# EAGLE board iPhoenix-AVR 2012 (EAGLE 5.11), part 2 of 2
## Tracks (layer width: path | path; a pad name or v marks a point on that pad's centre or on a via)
+5V  (via drill 0.5 pad 1.27)
  Top 0.254: v87.95,99.06 v92.71,94.3 | v53.66,73.03 v64.77,73.03 | v12.7,75.88 v12.7,66.67 | v31.75,37.15 v35.24,33.66 | v89.85,103.19 v96.52,103.19
  Bottom 0.406: 61.49,99.38 arc45 60.59,99.01 60.43,98.85 arc45 60.06,97.95 IC1.4 | 59.74,111.5 arc45 59.37,110.6 59.37,108.63 arc-45 59,107.74 56.96,105.69 arc45 56.81,105.34 IC1.20
  Bottom 0.61: 99.3,116.91 PS1.4 | LCD.2 | GLCD.4 | 68.58,95.37 R1.2 | LCD.2 | 154.3,84.14 153.67,84.77
  Bottom 0.813: 99.3,116.91 100.59,115.62 arc-45 100.96,114.73 100.96,111.44 R39.1 | C39.+ IC9.16 | 74.29,110.17 C35.1 arc90 69.53,108.59 69.53,106.25 arc45 69.9,105.36 arc-45 70.17,104.72 70.17,100.97 arc-90 C5.+ | 74.29,110.17 C36.+ 86.29,110.17 arc-45 87.5,109.67 89.33,107.84 arc-45 89.85,106.57 v89.85,103.19 89.85,101.49 arc-45 89.48,100.59 v87.95,99.06 | 74.29,110.17 IC8.8 | C1.2 61.49,99.38 | C2.2 59.74,111.5 | R30.2 19.31,39.42
  Bottom 1.016: R12.2 108.32,20.06 arc45 107.95,19.16 IC4.1 107.95,14.18 arc-45 107.58,13.28 C22.+ 106.68,6.67 | 100.33,86.04 C21.+ | 100.33,86.04 IC3.VCC 96.41,86.04 arc-45 95.51,86.41 92.45,89.48 arc-45 92.07,90.38 ISP.1 92.07,93.14 arc-45 92.45,94.03 v92.71,94.3 | 100.33,86.04 R15.2 | 100.96,111.44 C37.1 R35.2 | 64.13,123.51 LED1.A | 64.13,123.51 C2.2 67.42,115.89 arc-45 68.32,115.52 R34.2 C35.1 | C28.1 8.89,109.75 arc45 9.26,108.85 11.06,107.05 arc-45 11.43,106.15 11.43,101.81 arc-45 11.06,100.91 10.16,100.01 | C28.1 JBUZ.2 | LED12.A D2.C 10.16,100.01 | C32.+ C33.1 13.97,53.97 | C32.+ 16.62,60.01 arc-45 17.52,59.64 R32.2 | R29.2 IC7.8 14.92,53.02 | C34.2 C31.+ | IC9.10 141.6,91.01 arc45 141.98,90.12 144.41,87.68 arc45 145.31,87.31 C40.2 150.18,87.31 arc-45 151.8,86.64 153.67,84.77 | GLCD.4 36.2,16.08 arc-45 35.82,15.19 35.3,14.66 arc-45 34.4,14.29 32.91,14.29 arc45 32.01,13.92 31.49,13.39 arc45 31.11,12.49 LCD.2 31.11,6.88 arc45 31.49,5.98 33.28,4.18 arc45 34.18,3.81 JLEDD.2 | GLCD.4 36.19,18.84 arc45 35.82,19.74 34.66,20.9 arc-45 34.29,21.8 R52.E 34.29,32.7 v35.24,33.66 | 12.7,77.79 C19.1 5VA1.2 23.6,77.79 arc45 24.5,78.16 K1.1 34.29,84.14 | C1.2 C5.+ 68.58,95.37 | 41.91,87.31 43.18,87.31 | 43.18,87.31 46.39,87.31 arc-45 47.79,86.73 49.84,84.68 arc-45 50.8,82.36 50.8,77.26 arc45 51.77,74.91 v53.66,73.03 | 142.88,6.67 134.83,6.67 arc-45 133.93,7.04 R10.2 127.69,7.04 arc-45 126.79,6.67 124.35,6.67 arc-45 123.45,7.04 C26.1 IC5.1 119.38,7.83 arc-45 119.01,6.93 118.48,6.4 arc-45 117.58,6.03 107.31,6.03 | 142.88,6.67 R8.2 | 153.67,83.5 154.3,84.14 154.94,84.77 | 154.94,84.77 156.22,86.05 arc45 156.84,87.56 C39.+
  Bottom 1.016: 153.67,83.5 153.45,83.28 arc45 153.03,82.28 153.03,75.14 arc-45 152.66,74.24 152.14,73.71 arc-45 151.24,73.34 147.85,73.34 arc45 146.95,72.97 143.88,69.9 arc45 143.51,69.01 143.51,66.25 arc-45 143.14,65.35 142.61,64.82 arc-45 141.71,64.45 138.32,64.45 arc45 137.42,64.08 134.36,61.01 arc45 133.98,60.12 133.98,58.28 arc-90 131.27,55.56 128.8,55.56 arc45 127.9,55.19 127.4,54.7 arc45 126.74,53.09 126.74,52.97 arc45 127.19,51.88 127.23,51.84 arc45 128.98,51.12 140.47,51.12 arc-45 143.49,49.87 R25.A 149.17,44.5 arc-45 149.54,43.61 149.54,39.08 arc-45 149.08,37.95 148.57,37.44 arc45 148.27,36.73 148.27,33.55 arc-45 147.9,32.65 R17.A 148.42,30.96 arc-45 149.54,28.71 149.54,19.58 arc-45 149.17,18.68 147.69,17.2 arc45 147.32,16.3 147.32,9.73 arc-45 146.95,8.84 145.15,7.04 arc-45 144.25,6.67 142.88,6.67 | 106.04,6.03 107.31,6.03 | 106.04,6.03 97.1,6.03 arc-45 95.03,6.89 83.34,18.57 arc-45 82.55,20.49 R38.2 80.01,21.91 | 107.31,6.03 106.68,6.67 | 106.04,6.03 106.68,6.67 | 78.74,21.91 80.01,21.91 | 78.74,21.91 77.36,21.91 arc-45 76.46,22.28 74.35,24.39 arc45 73.45,24.77 71.33,24.77 arc-45 70.43,25.14 69.59,25.98 arc-45 69.21,26.88 C13.+ C14.1 IC2.30 69.21,41.7 arc-45 69.59,42.6 71.38,44.4 arc45 71.75,45.29 IC2.10 C12.1 71.75,56.31 arc-45 72.13,57.2 73.29,58.37 arc45 73.66,59.26 C11.+ 73.66,63.29 arc45 73.29,64.19 64.99,72.48 arc-45 v64.77,73.03 | 79.38,22.54 C38.2 | 80.01,21.91 79.38,22.54 | 78.74,21.91 79.38,22.54 | 64.13,123.51 LED2.A 39.26,123.51 arc45 38.36,123.14 PW1.3 C18.+ C17.+ C16.1 R7.2 | 13.97,53.97 13.97,53.02
  Bottom 1.016: 13.97,53.02 14.92,53.02 | 13.97,63.18 13.97,62.23 | 13.97,62.23 C32.+ | v12.7,66.67 13.6,65.78 arc-45 13.97,64.88 13.97,64.13 | 13.97,64.13 13.97,63.18 | 12.7,77.79 v12.7,75.88 | 13.97,63.18 13.02,63.18 | 13.02,63.18 JP8.1 | 19.31,39.42 arc-45 19.68,38.53 R31.2 18.79,36.25 arc45 18.41,35.35 IC6.8 17.07,34.93 arc45 16.12,34.53 15.62,34.04 arc45 15.24,33.11 C34.2 | 13.97,53.02 13.97,52.07 | 13.97,52.07 13.97,46.14 arc45 14.94,43.8 R30.2 | C34.2 25,32.38 arc45 28.39,33.79 v31.75,37.15 | R7.2 38.47,100.38 arc-45 37.57,100.01 22.06,100.01 arc41 21.23,99.71 19.72,98.41 arc-41 18.9,98.11 12.59,98.11 arc-45 11.69,98.48 10.16,100.01 | R7.2 41.22,101.34 arc-45 41.91,99.49 41.91,88.58 | 41.91,88.58 41.91,87.31 | 153.67,83.5 153.67,84.77 | 153.67,84.77 154.94,84.77 | 12.7,77.79 8.12,77.79 arc-45 7.22,78.16 +5V.2 | R39.1 100.33,109.11 arc-45 98.83,105.5 v96.52,103.19 | 41.91,87.31 40.64,87.31 | 40.64,87.31 37.17,87.31 arc45 36.2,86.91 34.58,85.29 arc45 34.29,84.6 34.29,84.14 | 34.29,84.14 D1.C | 41.91,88.58 40.64,87.31 | 41.91,88.58 43.18,87.31 | 13.97,64.13 13.02,63.18 | 13.02,63.18 13.97,62.23 | 14.92,53.02 13.97,52.07 | 13.97,53.97 14.92,53.02 | C28.1 8.91,115.25 SPK.1
+5V/1  (via drill 0.5 pad 1.27)
  Top 0.254: v40.96,107.63 v33.02,107.63
  Bottom 1.016: JP7.3 C3.1 30.74,108 arc45 31.64,107.63 v33.02,107.63 | R2.2 47.47,107.48 FB1.1 41.11,107.48 v40.96,107.63
A1
  Bottom 0.813: DSP1.13 128.27,122.3 arc-45 128.59,123.06 129.8,124.28 arc-45 131.01,124.78 141.71,124.78 arc-45 143.15,124.18 146.03,121.3 arc45 146.84,120.97 152.03,120.97 arc-45 153.74,120.26 R45.2
A2
  Bottom 0.813: DSP1.9 138.43,122.36 arc-90 139.57,123.51 141.4,123.51 arc-45 142.29,123.14 145.19,120.24 arc45 146.5,119.7 151.09,119.7 arc-45 152.24,119.22 R46.2
A2P
  Bottom 0.508: 139.16,108.27 135.97,108.27 arc90 134.62,106.92 134.62,105.28 arc-90 133.47,104.14
  Bottom 0.813: 139.16,108.27 arc-45 140.08,107.88 140.63,107.33 arc-45 140.97,106.52 DSP1.7
  Bottom 1.016: S7SEG1.1 128.27,101.39 arc-45 128.64,102.29 129.95,103.6 arc-45 131.26,104.14 133.47,104.14
A3
  Bottom 0.813: DSP1.4 133.35,107.5 arc-45 134.12,109.35 136.3,111.54 arc-45 138.37,112.39 143.79,112.39 arc45 147.1,113.77 R47.2
A4
  Bottom 0.813: R48.2 145.59,114.79 arc-45 142.87,113.66 134.56,113.66 arc45 132.49,112.81 129.07,109.38 arc45 128.27,107.45 DSP1.2
A5
  Bottom 0.813: R49.2 143.78,115.52 arc-45 142.36,114.94 134.18,114.94 arc45 131.67,113.9 126.41,108.63 arc45 125.73,106.99 DSP1.1
A6
  Bottom 0.61: 136.16,123.51 arc-90 137.16,122.5 137.16,120.12
  Bottom 0.813: DSP1.12 130.81,122.36 arc-90 131.95,123.51 136.16,123.51 | 137.16,120.12 arc45 137.91,118.31 139.55,116.67 arc45 140.67,116.2 141.92,116.2 arc90 R50.2
A7
  Bottom 1.016: R51.2 DSP1.5
A8
  Bottom 1.016: R53.2 DSP1.8
AR11
  Bottom 1.016: 75.59,116.55 RS1.1 R34.1 | 75.59,116.55 R37.2 | 75.59,116.55 76.46,115.68 arc-45 76.83,114.78 IC8.7
CB2
  Bottom 0.406: IC1.13 54.21,96.14 arc-45 53.84,95.24 arc-45 53.1,94.93 52.11,94.93 arc45 51.22,94.56 49.23,92.58
  Bottom 0.813: 49.23,92.58 arc45 JP2.2
CB3
  Bottom 0.406: IC1.14 53.56,96.47 arc-45 53.41,96.1 arc-45 52.51,95.73 50.15,95.73 arc45 49.26,95.35 46.73,92.83
  Bottom 0.813: 46.73,92.83 arc45 46.35,91.93 JP2.3
CB4
  Bottom 0.406: IC1.12 54.86,95.5 arc-45 54.49,94.6 54.3,94.41 arc-45 53.65,94.14 arc45 52.75,93.77 51.81,92.82
  Bottom 0.813: 51.81,92.82 arc45 51.43,91.93 JP2.1
CTS
  Bottom 0.406: IC1.11 55.51,94.86 arc-45 55.14,93.96 54.35,93.17
  Bottom 0.813: JP1.1 53.97,92.27 arc-45 54.35,93.17
  Bottom 1.016: JP1.1 S22.6
DCD
  Bottom 0.406: 56.16,92.11 IC1.10
  Bottom 0.813: 56.16,92.11 JP1.2
DSR
  Bottom 0.406: 59.05,91.87 JP1.3 | 58.68,92.76 57.18,94.27 arc-45 56.81,95.16 IC1.9
  Bottom 0.813: 58.68,92.76 arc-45 59.05,91.87
DTR
  Bottom 0.406: IC1.2 61.36,95.06 arc45 61.73,94.16 JP0.1
EPROM_WP  (via drill 0.5 pad 1.27)
  Top 0.254: v18.41,46.04 v18.41,49.21
  Bottom 0.813: S21.2 26.09,46.62 arc45 25.19,46.99 20.71,46.99 arc45 v18.41,46.04
  Bottom 1.016: IC7.7 R32.1 v18.41,49.21
GLCD-V0
  Bottom 1.016: GLCD.5 38.74,19.48 arc45 38.36,20.37 R52.S
GLCD-VEE  (via drill 0.5 pad 1.27)
  Top 0.254: v40,21.59 v71.75,21.59
  Bottom 0.61: GLCD.18
  Bottom 1.016: v71.75,21.59 GLCD.18 | v40,21.59 39.74,21.85 arc-45 39.37,22.75 R52.A
GND  (via drill 0.5 pad 1.27)
  Top 0.254: v42.86,121.6 v42.86,125.41 | v29.84,104.14 v29.84,98.11 | v40,98.11 v43.81,98.11 | v87.95,106.36 v90.17,109.54 | v86.2,98.27 v90.33,94.14 | v148.27,93.66 v151.45,95.88 | v155.89,97.16 v159.38,95.57 | v68.9,112.39 v68.9,117.47 | v104.46,4.13 v104.46,7.94 | v147.32,20.96 v151.45,20.96 | v48.89,80.64 v52.7,80.64 | v31.11,3.49 v34.29,5.71 | v43.81,76.52 v47.31,74.93 | v117.79,50.48 v122.55,50.48 | v72.07,42.23 v69.21,45.08
  Bottom 0.406: IC1.18 55.51,102.92 56.51,101.92 | IC1.21 57.46,102.23 57.15,101.92 | IC1.26 60.71,102.17 60.96,101.92 | IC1.25 60.06,102.29 59.69,101.92 | IC1.7 58.11,101.59 57.78,101.92 | v68.9,117.47 68.9,118.43 | v104.46,4.13 104.46,2.54 | v151.45,20.96 153.35,20.96
  Bottom 0.508: 140.97,13.39 141.87,14.29 145.41,14.29
  Bottom 0.61: C38.1 | LCD.16 68.9,11.75 69.85,12.7 72.39,12.7 76.83,16.19 GLCD.20 | v147.32,20.96 147.32,20 | LCD.1 | LCD.1 | 132.55,13.2 137.81,8.25 139.55,8.25 140.97,9.36 | C35.2 71.66,108.18 arc-45 73.42,108.9 84.45,108.9 C36.- 85.09,107 R33.1 85.41,97.16 v86.2,98.27 | ISP.2 89.53,93.98 91.76,96.2 93.34,96.2 | C16.2 31.11,105.09 | v42.86,125.41 42.23,125.41 | v43.81,98.11 C10.2 | v40,98.11 39.37,98.11 | 87.63,104.78 v87.95,106.36 | v90.33,94.14 90.49,93.66 90.17,93.35 | 37.15,82.87 37.15,83.19 36.51,83.82
  Bottom 0.813: C8.2 C9.2 | v159.38,95.57 159.7,96.2
  Bottom 1.016: Q7.1 121.92,112.08 Q8.1 115.57,114.62 113.66,116.52 Q9.1 105.41,117.79 | IC4.3 102.87,13.65 C22.- 104.14,8.25 v104.46,7.94 | R26.2 C29.2 128.27,11.75 129.54,13.02 C25.2 LDR.2 132.55,13.2 | R26.2 C26.2 | R26.2 121.92,14.29 D4.C | 145.1,27.62 C27.1 | 145.1,27.62 146.68,27.62 R17.E v147.32,20.96 145.41,19.05 C24.1 145.41,14.29 145.41,10.48 NTC.1 | C30.1 146.68,41.59 R25.E 145.1,38.74 145.1,27.62 | C21.- IC3.GND 95.88,88.58 94.61,89.85 94.61,94.93 93.34,96.2 | C39.- 152.4,88.58 151.13,89.85 C40.1 IC9.13 149.22,92.71 v148.27,93.66 | C18.- C17.- C16.2 30.8,105.09 v29.84,104.14 | Q4.1 22.86,103.82 24.76,105.73 LED11.K 26.67,106.36 C3.2 31.11,105.09 | JP8.2 C20.2 | C32.- C33.2 11.43,54.29 10.16,53.02 IC7.1 IC7.2 IC7.3 IC7.4 8.89,31.11 10.16,29.85 C31.- | IC6.4 26.03,28.57 24.76,29.85 C34.1 C31.- | IC2.11 C12.2 69.21,56.83 71.12,58.74 C11.- 71.12,63.82 69.85,65.09 C6.2 C7.2 62.86,73.4 arc-90 64.72,75.25 71.75,75.25 | C4.1 71.75,75.25 | 71.75,75.25 71.75,77.81 | R40.1 89.29,116.91 PS1.3 92.48,118.2 93.34,119.06 102.23,119.06 103.5,117.79 105.41,117.79 | R40.1 IC8.5 | 105.41,117.79 C37.2 | IC2.31 C14.2 C13.- 74.29,27.62 | C38.1 76.83,25.08 74.29,27.62 | 74.29,27.62 C15.2 | R36.1 26.67,7.94 28.57,9.84 LCD.1 | GND.1 GND.2 5VA1.1 C19.2 14.31,74 | C5.- C1.1 60.96,101.92 59.69,101.92 57.78,101.92 57.15,101.92 56.51,101.92 | 140.97,9.36 140.97,13.39 | Q6.1 131.44,99.06 132.71,97.79 137.48,97.79 IC9.8 | C31.- 11.43,19.37 BAT.- | R3.2 41.91,113.35 40,115.25 40,118.75 v42.86,121.6 | v29.84,98.11 30.48,97.79 | R40.1 87.63,112.71 v90.17,109.54 | v151.45,95.88 v155.89,97.16 | R6.2 arc45 66.49,108.08 67.98,109.57 arc45 68.9,111.79 v68.9,112.39
  Bottom 1.016: 40,80.01 42.23,80.01 v43.81,76.52 | v47.31,74.93 v48.89,80.64 | v52.7,80.64 54.29,80.64 | S20.4 S20.3 | S18.4 S18.3 | S19.3 48.62,64.81
  Bottom 1.676: 1.59,80.64 1.59,95.88
  pour Bottom (isolate 0.711): 166.69,134.3 168.27,-6.03 -6.99,-7.3 -8.57,81.91 18.73,81.91 22.86,86.36 22.86,95.25 5.4,96.2 5.4,93.98 -8.57,93.98 -8.57,133.03
GROUP-A1
  Bottom 1.016: R23.1 JRLY.2
IR
  Bottom 1.016: JRC5R.1 R15.1 98.32,91.76 arc45 97.42,91.39 IC3.OUT
LCDA
  Bottom 0.61: R38.1 | GLCD.19
  Bottom 0.813: LCD.15 64.13,12.17 arc-45 64.51,13.07 65.03,13.6 arc-45 65.93,13.97 70.93,13.97 arc45 71.83,14.34 73.92,16.44 arc45 74.29,17.34 GLCD.19
  Bottom 1.016: GLCD.19 R38.1
LDR
  Bottom 1.016: R14.2 130.68,20.77 arc45 129.47,21.27 JDAC3.1 128.27,20.53 arc45 128.64,19.63 129.17,19.1 arc-45 129.54,18.21 C25.1
LM35-1
  Bottom 1.016: JDAC5.1 120.12,21.27 arc-45 121.02,20.9 124.09,17.83 arc-45 124.46,16.94 R19.2 C29.1
LM35-2
  Bottom 1.016: JDAC6.2 D3.A 113.03,17.99 arc-45 112.66,17.09 arc45 112.39,16.46 112.39,15.93 arc45 112.66,15.29 arc-45 113.03,14.4 IC5.3
N$1
  Bottom 1.016: Q5.1 IC6.1
N$2
  Bottom 0.61: Q1.1 67.94,58.86
  Bottom 1.016: IC2.12 66.67,57.07 arc-45 67.05,57.97 Q1.1 | 67.94,58.86 C6.1
N$3
  Bottom 1.016: SG1.+ 4.18,110.28 arc-45 3.81,111.17 JBUZ.1
N$4
  Bottom 1.016: JP8.3 C20.1 R9.2
N$5
  Bottom 1.016: R9.1 JDAC4.2
N$6  (via drill 0.6 pad 1.27)
  other vias: 3.49,124.46
N$7
  Bottom 1.016: Q5.2 IC6.2
N$8
  Bottom 1.016: C15.1 IC2.32
N$9
  Bottom 1.016: BAT.+ 23.87,15.5 arc-45 23.49,16.4 IC6.3
N$10  (via drill 0.6 pad 1.27)
  other vias: 158.43,124.46
N$11  (via drill 0.6 pad 1.27)
  other vias: 158.43,3.81
N$12  (via drill 0.6 pad 1.27)
  other vias: 3.49,3.81
N$13
  Bottom 0.61: X1.S2 46.68,116.54
  Bottom 1.016: 46.68,116.54 arc-45 50.49,118.11 54.91,118.11 arc-45 X1.S1 | R3.1 42.49,116.89 arc45 43.39,116.52 X1.S2
N$14
  Bottom 1.016: LED11.A 26.62,102.61 arc45 27.51,102.23 R7.1
N$15
  Bottom 1.016: JP7.1 27.76,116.52 arc45 26.86,116.15 J1.1
N$16
  Bottom 1.016: JP7.2 30.59,113.98 arc45 31.49,114.35 32.01,114.88 arc45 32.38,115.78 32.38,117.27 arc-45 32.76,118.16 33.92,119.33 arc45 34.29,120.22 PW1.2
N$17  (via drill 0.6 pad 1.27)
  other vias: 80.96,64.45
N$36
  Bottom 1.016: S2.2 S3.1
N$37
  Bottom 1.016: S3.2 S4.1
N$38
  Bottom 1.016: S4.2 S5.1
N$39
  Bottom 1.016: S10.2 S11.1
N$40
  Bottom 1.016: S11.2 S12.1
N$41
  Bottom 1.016: S12.2 S13.1
N$60
  Bottom 1.016: S6.2 S7.1
N$61
  Bottom 1.016: S7.2 S8.1
N$62
  Bottom 1.016: S8.2 S9.1
N$63
  Bottom 0.61: LCD.3
  Bottom 1.016: R36.2 LCD.3
N$65
  Bottom 1.016: S14.2 S15.1
N$66
  Bottom 1.016: S15.2 S16.1
N$67
  Bottom 1.016: S2.4 126.1,77.09 arc45 125.73,76.19 125.73,73.87 arc-45 125.36,72.97 123.84,71.45 arc-45 122.94,71.08 S6.3
N$68
  Bottom 1.016: S7.3 133.61,72.69 arc45 133.98,73.59 133.98,75.99 arc-45 134.36,76.89 137.07,79.6 arc-45 137.96,79.97 S3.4
N$69
  Bottom 1.016: S8.3 141.99,71.08 arc45 142.89,71.45 145.04,73.61 arc45 145.41,74.5 145.41,76.83 arc-45 145.79,77.73 S4.4
N$70
  Bottom 1.016: S5.4 154.99,77.41 arc45 154.62,76.51 154.62,74.19 arc-45 154.25,73.29 152.42,71.45 arc-45 151.52,71.08 S9.3
N$71
  Bottom 1.016: S16.2 S17.1
N$73
  Bottom 0.61: S14.3 123.58,53.3 arc45 124.48,53.67 126.63,55.83 arc45 127,56.72 127,59.68 arc-45 127.37,60.58 S10.4
N$74
  Bottom 1.016: S11.4 136.65,60.34 arc45 135.89,58.5 135.89,57.2 arc-45 135.18,55.49 133.69,54 arc-45 S15.3
N$75
  Bottom 1.016: S16.3 141.99,53.3 arc45 142.89,53.67 144.41,55.19 arc45 144.78,56.09 144.78,58.41 arc-45 145.15,59.31 S12.4
N$76
  Bottom 1.016: S13.4 154.68,59.31 arc45 154.3,58.41 154.3,56.09 arc-45 153.93,55.19 152.42,53.67 arc-45 151.52,53.3 S17.3
N$77
  Bottom 1.016: S6.4 arc45 128.24,70.78 125.47,68 arc45 125.09,67.1 125.09,64.98 arc-45 124.72,64.08 122.83,62.19 S10.3
N$78
  Bottom 1.016: S11.3 132.47,62.19 arc45 133.37,62.56 135.52,64.72 arc45 135.89,65.61 135.89,67.94 arc-45 136.26,68.84 S7.4
N$79
  Bottom 1.016: S8.4 145.79,68.84 arc45 145.41,67.94 145.41,65.61 arc-45 145.04,64.72 142.89,62.56 arc-45 141.99,62.19 S12.3
N$80
  Bottom 1.016: S9.4 154.68,68.2 arc45 154.3,67.3 154.3,64.45 152.42,62.56 arc-45 151.52,62.19 S13.3
N$81
  Bottom 0.813: IC9.15 154.3,92.5 arc-45 154.68,93.4 158.38,97.1 arc45 158.75,98 158.75,99.49 arc45 158.38,100.38 156.58,102.18 arc-45 156.21,103.08 R45.1
N$82
  Bottom 0.813: IC9.1 arc45 156.62,99.92 154.04,102.5 arc-45 153.67,103.4 R46.1
N$83
  Bottom 0.813: IC9.2 154.3,99.49 arc45 153.93,100.38 151.5,102.82 arc-45 151.13,103.71 R47.1
N$84
  Bottom 0.813: IC9.3 151.76,100.12 arc45 151.39,101.02 148.96,103.45 arc-45 148.59,104.35 R48.1
N$95
  Bottom 0.813: IC9.4 149.22,100.76 arc45 148.85,101.65 146.42,104.09 arc-45 146.05,104.98 R49.1
N$96
  Bottom 0.813: IC9.5 146.68,101.39 arc45 146.31,102.29 144.52,104.09 arc-45 144.14,104.98 144.14,108.38 arc45 143.77,109.27 R50.1
N$100
  Bottom 0.813: IC9.6 R51.1
N$103
  Bottom 1.016: R33.2 LED14.K
N$113
  Bottom 0.813: IC9.7 141.6,103.61 arc-45 141.98,104.51 142.19,104.72 arc45 142.56,105.62 142.56,106.79 arc45 142.19,108 141.02,109.17 arc-45 140.97,109.43 R53.1
N$114
  Bottom 1.016: Q9.3 DSP1.14
N$115
  Bottom 0.61: 133.35,121.49 DSP1.11
  Bottom 0.813: 133.35,121.49 arc-90 131.55,119.7 121.53,119.7 arc45 120.03,119.07 Q8.3
N$116
  Bottom 0.813: DSP1.10 135.89,121.38 arc-45 135.6,120.67 133.94,119.02 arc-45 132.52,118.43 129.15,118.43 arc45 127.65,117.8 Q7.3
N$117
  Bottom 1.016: Q6.3 136,100.01 arc45 136.9,100.38 138.06,101.55 arc45 138.43,102.44 DSP1.6
N$118
  Bottom 0.406: 125.73,99.27 S7SEG1.2 | 126.1,98.37 126.31,98.16 arc45 127.21,97.79 130.28,97.79 arc-45 131.18,97.42 132.98,95.62 arc45 133.88,95.25 148.7,95.25 arc-45 149.6,94.88
  Bottom 0.813: 149.6,94.88 151.39,93.08 arc-45 151.76,92.18 IC9.14
  Bottom 1.016: 126.1,98.37 arc-45 125.73,99.27
N$119
  Bottom 0.406: 145.47,93.93 arc45 144.57,94.3 133.4,94.3 arc-45 132.5,94.67 130.71,96.47 arc45 129.81,96.84 125.62,96.84 arc-45 124.72,97.21 123.56,98.37 | 123.19,99.27 S7SEG1.3
  Bottom 0.813: 145.47,93.93 146.31,93.08 arc-45 146.68,92.18
  Bottom 1.016: 146.68,92.18 IC9.12 | 123.56,98.37 arc-45 123.19,99.27
N$120
  Bottom 0.406: 120.65,99.27 S7SEG1.4 | 121.02,98.37 123.29,96.1 arc45 124.19,95.73 129.33,95.73 arc-45 130.23,95.35 131.87,93.72 arc45 132.76,93.35 143.14,93.35 arc-45 143.77,93.08 arc-45 144.14,92.18
  Bottom 1.016: 121.02,98.37 arc-45 120.65,99.27 | 144.14,92.18 IC9.11
N$122
  Bottom 1.016: R44.1 Q9.2
N$123
  Bottom 1.016: R43.1 Q8.2
N$124
  Bottom 1.016: R42.1 Q7.2
N$125
  Bottom 1.016: Q6.2 R41.1
N$126
  Bottom 0.813: S7SEG1.5 118.11,100.12 arc-45 118.48,101.02 119.01,101.55 arc-45 119.91,101.92 R41.2
N$127
  Bottom 0.813: S7SEG1.6 115.57,99.55 arc-45 115.94,100.45 120.85,105.36
  Bottom 1.016: 120.85,105.36 arc-45 121.75,105.73 R42.2
N$128
  Bottom 0.813: R43.2 116.2,103.4 arc-45 115.83,102.5 113.25,99.92 arc45 S7SEG1.7
N$129
  Bottom 1.016: S7SEG1.8 R44.2
N$130
  Bottom 1.016: IC5.2 R26.1 R19.1
N$131
  Bottom 1.016: D4.A 116.47,18.36 arc-45 117.37,18.73 D3.C
N$132
  Bottom 1.016: R17.S R16.2
N$137
  Bottom 1.016: J1W.1 R12.1 102.98,21.27 arc-45 103.88,20.9 105.04,19.74 arc-45 105.41,18.84 IC4.2
N$146
  Bottom 1.016: R13.1 R8.1 151.13,11.32 arc-45 150.76,10.42 NTC.2
N$152
  Bottom 1.016: R24.2 154.06,44.37 arc45 156.18,43.5 R25.S
N$153
  Bottom 1.016: JAN1.2 C27.2 R16.1
N$154
  Bottom 1.016: R24.1 141.87,48.31 arc-45 142.24,47.42 C30.2 JAN2.2
N$155
  Bottom 1.016: R10.1 138.33,10.9 arc-45 137.95,11.8 LDR.1 137.95,19 arc-45 138.33,19.9 R14.1
N$161
  Bottom 0.406: IC1.23 58.76,105.25 arc-45 58.89,105.56 59.19,105.86 arc-45 59.64,106.04 59.88,106.04 arc45 60.1,106.14 60.32,106.36
  Bottom 0.61: 60.32,106.36 64.04,110.08 arc-45 65.8,110.81
  Bottom 0.813: 65.8,110.81 R4.1
N$163
  Bottom 1.016: SG1.- Q4.3 | D2.A 13.87,100.12 arc-45 13.49,101.01 SG1.- | SG1.- 11.8,109.32 arc-45 11.43,110.22 C28.2 11.43,118.4 arc-45 11.8,119.3 SPK.2
N$164
  Bottom 1.016: Q4.2 R27.2
N$165
  Bottom 1.016: R27.1 JSPK.2
N$197
  Bottom 0.406: 51.59,100.65 arc45 52.49,101.02 53.84,102.37 arc45 54.21,103.27 IC1.16 54.21,106 arc45 54.12,106.22 54.07,106.27 arc-45 53.97,106.49 53.97,107
  Bottom 0.61: 53.97,107 53.97,111.13
  Bottom 0.8: 53.97,111.13 53.97,111.79 X1.2
  Bottom 0.813: C8.1 51.59,100.65
N$199
  Bottom 0.406: 52.39,103.19 53.17,103.19 arc90 53.56,103.57 IC1.15 53.56,105.28 arc45 53.4,105.67 52.97,106.1 arc-45 52.7,106.73 52.7,107.32 | 52.7,110.49 52.7,112.32 arc-45 52.98,112.99 53.5,113.51
  Bottom 0.61: 52.7,107.32 52.7,110.49
  Bottom 0.8: X1.3 53.94,113.81 arc45 53.71,113.72 53.5,113.51
  Bottom 0.813: C9.1 52.39,103.19
N$200
  Bottom 0.406: 51.9,99.06 54.49,101.65 arc45 54.86,102.54 IC1.17
  Bottom 0.813: C10.1 50.96,98.11 51.9,99.06
N$201
  Bottom 0.406: IC1.19 56.16,106.64
  Bottom 0.61: 56.16,106.64 56.16,107.35 R2.1
  Bottom 0.813: R2.1 R6.1
N$202
  Bottom 0.406: 60.48,108.27 | IC1.22 58.11,105.37 arc-45 58.48,106.27 60.48,108.27
  Bottom 0.813: 60.48,108.27 60.9,108.68 arc45 61.59,110.37 R5.1
N$203
  Bottom 1.016: LED1.K R4.2
N$228
  Bottom 0.61: 80.64,117.16 80.62,117.18
  Bottom 1.016: 80.62,117.18 RS1.2 R40.2 | R37.1 80.64,117.16 79.75,116.26 arc45 79.38,115.36 IC8.6
N$235
  Bottom 1.016: LED2.K R5.2
N$236
  Bottom 1.016: C23.1 112.39,39.8 arc-45 112.77,40.69 R11.E
N$238
  Bottom 1.016: Q3.2 R28.2 R23.2
N$239
  Bottom 1.016: LED12.K 18.82,96.2 arc-45 21.38,95.14 R18.2
N$240
  Bottom 1.016: R18.1 K1.2 Q3.3 D1.A
N$241
  Bottom 1.778: QR1.2 10.88,90.46 arc45 11.78,90.83 K1.O
N$254
  Bottom 1.778: K1.P 18.31,91.76 arc45 17.41,91.39 11.8,85.78 arc-45 10.9,85.41 6.53,85.41 QR1.1
N$288
  Bottom 1.016: JLEDD.1 RN1.1
N$293
  Bottom 0.61: 46.41,4.71 arc45 44.88,5.4 44.02,5.4 arc-45 43.13,5.77
  Bottom 1.016: 46.41,4.71 RN1.2 | LED3.A 43.13,5.77
N$294
  Bottom 1.016: RN1.3 arc45 49.62,4.35 47.53,6.44 arc45 LED4.A
N$295
  Bottom 1.016: RN1.4 52.39,5.51 arc45 52.02,6.4 LED5.A
N$296
  Bottom 1.016: RN1.5 54.93,4.55 arc-45 55.3,5.45 LED6.A
N$297
  Bottom 1.016: RN1.9 73.45,3.81 arc45 74.35,4.18 75.19,5.03 arc45 75.56,5.92 LED10.A
N$298
  Bottom 0.61: 62.82,3.92 63.57,4.68 arc-45 64.93,5.24 68.69,5.24
  Bottom 0.813: 68.69,5.24 arc45 70.06,5.93 | RN1.8 arc45 62.82,3.92
  Bottom 1.016: 70.06,5.93 LED9.A
N$299
  Bottom 0.61: 64.34,6.67 64.19,6.67 arc45 63.55,6.4 62.63,5.48 arc-45 62.05,5.24 61.77,5.24 arc45 60.88,4.68
  Bottom 0.813: RN1.7 60.88,4.68
  Bottom 1.016: 64.34,6.67 LED8.A
N$303
  Bottom 1.016: RN1.6 arc-45 57.69,4.35 59.64,6.3 arc-45 60.53,6.67 LED7.A
NTC
  Bottom 1.016: JDAC2.1 C24.2 R13.2
P25
  Bottom 1.016: PS1.5 92.48,111.85 R39.2 JPS.3
P43
  Bottom 0.61: 94.61,116.88 PS1.1
  Bottom 1.016: R35.1 JPS.1 94.61,116.88
PA0
  Bottom 0.61: JP6.1 arc45 95.38,31.75 133.14,31.75
  Bottom 1.016: JP6.1 IC2.40 | 133.14,31.75 arc-45 134.04,31.38 137.42,27.99 arc45 138.32,27.62 JAN1.1
PA1
  Bottom 0.61: 100.91,33.39 arc45 101.81,33.02 130.28,33.02 arc45 131.18,33.71
  Bottom 1.016: 100.91,33.39 96.57,37.73 arc45 95.68,38.1 93.7,38.1 arc45 92.8,37.73 92.45,37.37 arc45 92.07,36.47 IC2.39 JP6.2 | 131.18,33.71 JAN2.1
PA2
  Bottom 0.61: 132.45,30.11 arc45 131.55,30.48 90.49,30.48 arc-90 89.53,31.43
  Bottom 1.016: IC2.38 JP6.3 89.53,31.43 | 132.45,30.11 136.42,26.14 arc45 142.03,23.81 JDAC2.2
PA3
  Bottom 1.016: JDAC1.2 100.7,40.06 arc-45 99.8,39.69 89.49,39.69 arc45 88.59,39.32 87.37,38.09 arc45 86.99,37.19 IC2.37 JP6.4
PA4
  Bottom 0.61: 123.24,28.84 arc45 122.35,29.21 86.64,29.21 arc-50 85.66,29.67 84.75,30.76
  Bottom 1.016: IC2.36 JP6.5 84.45,31.57 arc40 84.75,30.76 | 123.24,28.84 JDAC3.2
PA5
  Bottom 0.61: 82.24,30.75 84.39,28.36 arc48 85.34,27.94 111.55,27.94 arc-45 112.45,27.57
  Bottom 1.016: IC2.35 JP6.6 81.91,31.6 arc42 82.24,30.75 | 112.45,27.57 JDAC5.2
PA6
  Bottom 0.61: 79.38,31.65 JP6.7 | 79.71,30.79 83.14,27.08 arc47 84.07,26.67 109.65,26.67 arc-45 110.54,26.3
  Bottom 1.016: JP6.7 IC2.34 | 79.71,30.79 arc-43 79.38,31.65 | 110.54,26.3 JDAC6.1
PA7
  Bottom 0.61: JP6.8 76.83,31.96 | 77.21,31.06 82.5,25.77 arc45 83.39,25.4 96.95,25.4 arc-45 97.84,25.03
  Bottom 1.016: JP6.8 IC2.33 | 76.83,31.96 arc45 77.21,31.06 | 97.84,25.03 J1W.2
PB0  (via drill 0.5 pad 1.27)
  Top 0.254: v124.14,87.63 v128.27,87.63
  Bottom 0.61: S2.3 122.48,81.31 arc-45 122.85,82.21 123.77,83.13 arc45 124.14,84.03 v124.14,87.63 124.03,87.63 arc45 123.14,87.26 122.61,86.73 arc-45 121.71,86.36 120.86,86.36 arc45 119.96,85.99 94.99,61.01 arc45 94.61,60.12
  Bottom 0.813: JP3.1 94.61,60.12
  Bottom 1.016: IC2.1 JP3.1 | v128.27,87.63 S7SEG1.16
PB1
  Bottom 0.61: 92.07,59.48 arc-45 92.45,60.38 119.33,87.26 arc-45 120.22,87.63 121.08,87.63 arc45 121.97,88
  Bottom 0.813: JP3.2 92.07,59.48 | 121.97,88 S7SEG1.15
  Bottom 1.016: JP3.2 IC2.2 | S7SEG1.15 125.73,84.66 arc45 126.1,83.77 127.26,82.6 arc45 128.16,82.23 129.65,82.23 arc-45 130.55,81.86 131.7,80.71 arc-45 S3.3
PB2  (via drill 0.5 pad 1.27)
  Top 0.254: v133.03,38.42 v135.89,35.56
  Bottom 0.406: 124.72,93.29 arc-45 125.62,93.66 128.38,93.66 arc-45 129.28,93.29 135.52,87.05 arc-45 135.89,86.15 | 135.52,72.34 132.45,69.27 arc-45 131.55,68.9 128.8,68.9 arc45 127.9,68.53 127.37,68 arc45 127,67.1 127,64.98 arc-45 126.63,64.08 124.83,62.28 arc45 124.46,61.39 124.46,57.79 arc-90 122.87,56.2 121.86,56.2 arc90 119.38,53.72 119.38,45.25 arc45 120.62,42.26 123.17,39.7 | 141.45,80.48 arc-45 141.53,80.3
  Bottom 0.61: 89.53,58.85 arc-45 89.91,59.74 118.69,88.53 arc-45 119.59,88.9 119.81,88.9 arc45 120.7,89.27
  Bottom 0.813: 89.53,58.85 JP3.3 | 120.7,89.27 S7SEG1.14 | 135.89,75.36 135.89,73.23 arc-45 135.52,72.34
  Bottom 1.016: JP3.3 IC2.3 | JAN1.3 138.75,32.7 v135.89,35.56 | S7SEG1.14 124.72,93.29 | 135.89,86.15 135.89,84.03 arc45 136.26,83.13 136.56,82.83 arc45 138,82.23 139.17,82.23 arc-45 140.07,81.86 141.45,80.48 | 135.89,75.36 arc-45 136.26,76.25 137.42,77.42 arc-45 138.32,77.79 138.82,77.79 arc45 139.72,78.16 S4.3 141.53,80.3 | 123.17,39.7 arc45 124.07,39.33 S20.2 S20.1 131.24,39.33 arc-45 132.74,38.71 v133.03,38.42
PB3
  Bottom 0.406: 123.14,94.24 arc-45 124.03,94.62 129.01,94.62 arc-45 129.91,94.24 136.3,87.85 arc45 138.37,87
  Bottom 0.61: 86.99,58.21 arc-45 87.37,59.11 118.06,89.8 arc-45 118.95,90.17 arc45 119.14,90.25 S7SEG1.13 | 124.4,41.59 arc-45 122.33,42.45 121.57,43.22 arc-45 120.65,45.43 120.65,53.34 arc-90 122.24,54.93 123.3,54.93 arc45 124.2,55.3 125.36,56.46 arc45 125.73,57.36 125.73,60.75 arc-45 126.1,61.65 128.53,64.08 arc-45 129.43,64.45 132.19,64.45 arc45 133.09,64.82 133.61,65.35 arc45 133.98,66.25 133.98,68.37 arc-45 134.36,69.27 138.06,72.97 arc-45 138.96,73.34
  Bottom 0.813: 86.99,58.21 JP3.4
  Bottom 1.016: JP3.4 IC2.4 | S5.3 151.05,80.4 149.6,81.86 arc45 148.7,82.23 146.68,82.23 | S7SEG1.13 123.14,94.24 | JAN2.3 138.32,46.67 arc45 137.42,46.3 133.8,42.68 arc-45 131.18,41.59 124.4,41.59 | 138.96,73.34 141.71,73.34 arc45 142.61,73.71 143.14,74.24 arc45 143.51,75.14 143.51,77.85 arc-45 144.37,79.91 146.68,82.23 | 138.37,87 140.42,87 arc-45 142.98,85.93 146.68,82.23
PB4
  Bottom 0.61: 84.45,57.58 arc-45 84.83,58.47 S7SEG1.12 | 120.9,84.49 arc45 120,84.12 96.89,61.01 arc45 96.52,60.12 96.52,50.37 arc-45 96.15,49.48 95.62,48.95 arc-45 94.72,48.58 86.25,48.58 arc-45 85.35,48.95 84.83,49.48
  Bottom 0.813: JP3.5 84.45,57.58 | 120.9,84.49 S2.1 | 84.83,49.48 arc-45 84.45,50.37 IC2.5
  Bottom 1.016: IC2.5 JP3.5
PB5  (via drill 0.5 pad 1.27)
  Top 0.254: v94.61,100.97 v92.07,98.42
  Bottom 0.61: 81.91,56.94 arc-45 82.29,57.84 115.57,91.12 S7SEG1.11 115.57,92.18 | 113.91,75.6 arc45 113.01,75.23 98.16,60.38 arc45 97.79,59.48 97.79,49.74 arc-45 97.42,48.84 96.26,47.68 arc-45 95.36,47.31 84.98,47.31 arc-45 84.08,47.68 82.29,49.48
  Bottom 0.813: JP3.6 81.91,56.94 | 113.91,75.6 S6.1 | 82.29,49.48 arc-45 81.91,50.37 IC2.6
  Bottom 1.016: IC2.6 JP3.6 | JPS.2 v94.61,100.97 99.96,95.62 arc45 100.86,95.25 112.5,95.25 arc-45 113.4,94.88 115.2,93.08 arc-45 115.57,92.18 | v92.07,98.42 87.37,93.72 arc45 86.99,92.82 ISP.3
PB6
  Bottom 0.61: 113.03,91.01 arc-45 112.66,90.12 79.75,57.2 arc45 79.38,56.31 | 106.93,66.71 arc45 106.03,66.34 99.43,59.74 arc45 99.06,58.85 99.06,49.1 arc-45 98.69,48.21 96.89,46.41 arc-45 95.99,46.04 83.71,46.04 arc-45 82.81,46.41 79.75,49.48 | S7SEG1.10 113.03,91.87
  Bottom 0.813: 113.03,91.01 S7SEG1.10 | JP3.7 79.38,56.31 | 106.93,66.71 S10.1 | 79.75,49.48 arc-45 79.38,50.37 IC2.7
  Bottom 1.016: IC2.7 JP3.7 | 92.07,100.97 JPS.4 | 113.03,91.87 arc45 112.66,92.76 112.13,93.29 arc45 111.23,93.66 99.9,93.66 arc-45 99.01,94.03 92.07,100.97 | 92.07,100.97 84.83,93.72 arc45 84.45,92.82 ISP.4
PB7
  Bottom 0.61: 77.47,56.83 110.12,89.48 arc45 110.49,90.38 | 103.12,57.82 arc45 102.22,57.45 100.7,55.93 arc45 100.33,55.04 100.33,48.47 arc-45 99.96,47.57 97.53,45.14 arc-45 96.63,44.77 82.44,44.77 arc-45 81.54,45.14 77.21,49.48
  Bottom 0.813: 110.49,90.38 S7SEG1.9 | 103.12,57.82 S14.1 | 77.21,49.48 arc-45 76.83,50.37 IC2.8
  Bottom 1.016: IC2.8 JP3.8 76.83,55.67 arc-45 77.21,56.57 77.47,56.83 77.47,84.88 arc-45 77.84,85.78 80.96,88.9 81.41,89.35 arc45 81.91,90.56 ISP.5 JP9.2 | S7SEG1.9 JRC5R.2
PC0  (via drill 0.5 pad 1.27)
  Top 0.254: v48.89,40.64 v42.86,46.99
  Bottom 0.406: 44.45,9.58 44.71,9.84 arc45 45.08,10.74 45.08,13.13 | GLCD.9
  Bottom 0.61: JP4.1 | 45.08,13.13 arc-45 46.09,14.34 | v42.86,46.99 39.11,50.75 arc45 38.21,51.12 31.64,51.12 arc-45 30.74,51.49 30.22,52.02
  Bottom 0.813: 43.55,9.21 arc45 44.45,9.58 | 30.22,52.02 arc-45 29.84,52.91 S21.6
  Bottom 1.016: GLCD.9 JP4.1 | JP4.1 IC2.22 v48.89,40.64 | LED3.K 43.55,9.21 | 46.09,14.34 48.52,16.77 arc45 48.89,17.67 GLCD.9
PC1  (via drill 0.5 pad 1.27)
  Top 0.254: v50.48,41.91 v44.13,48.26
  Bottom 0.406: 49.79,9.79 arc45 50.16,10.69 50.16,13.76 | GLCD.10
  Bottom 0.61: JP4.2 | v44.13,48.26 40.54,51.86 arc45 39.64,52.23 33.7,52.23 arc-45 32.81,52.6
  Bottom 0.813: 48.69,9.21 arc45 49.58,9.58 49.79,9.79 | 32.81,52.6 S21.5
  Bottom 1.016: GLCD.10 JP4.2 | JP4.2 IC2.23 51.43,40.43 arc45 51.06,41.33 v50.48,41.91 | LED4.K 48.69,9.21 | 50.16,13.76 arc-45 50.54,14.98 51.06,15.5 arc45 51.43,16.4 GLCD.10
PC2
  Bottom 0.406: LCD.11
  Bottom 0.61: GLCD.11 | JP4.3
  Bottom 1.016: GLCD.11 LCD.11 53.97,11 arc-45 53.6,10.11 53.08,9.58 arc-45 52.18,9.21 LED5.K | GLCD.11 JP4.3 | JP4.3 IC2.24
PC3
  Bottom 0.406: LCD.12
  Bottom 0.61: GLCD.12 | JP4.4
  Bottom 1.016: GLCD.12 LCD.12 LED6.K | GLCD.12 JP4.4 | JP4.4 IC2.25
PC4
  Bottom 0.406: LCD.13
  Bottom 0.61: GLCD.13 | JP4.5
  Bottom 1.016: GLCD.13 LCD.13 59.05,11 arc45 59.43,10.11 59.95,9.58 arc45 60.85,9.21 LED7.K | GLCD.13 JP4.5 | JP4.5 IC2.26
PC5
  Bottom 0.406: LCD.14
  Bottom 0.61: GLCD.14 | 61.6,12.38 61.59,12.38 LCD.14 | LCD.14
  Bottom 0.813: 64.03,9.21 arc-45 63.13,9.58 61.59,11.11 LCD.14
  Bottom 1.016: IC2.27 JP4.6 GLCD.14 | 61.6,12.38 GLCD.14 | 64.03,9.21 LED8.K
PC6  (via drill 0.5 pad 1.27)
  Top 0.254: v70.8,11.11 v66.36,15.56
  Bottom 0.406: GLCD.15
  Bottom 0.61: GLCD.15
  Bottom 1.016: IC2.28 JP4.7 Q2.2 GLCD.15 | LED9.K v70.8,11.11 | v66.36,15.56 65.84,15.56 64.13,17.27 GLCD.15
PC7  (via drill 0.5 pad 1.27)
  Top 0.254: v73.34,10.8 v68.58,15.56
  Bottom 0.406: 73.45,10.8 v73.34,10.8
  Bottom 0.61: GLCD.16
  Bottom 1.016: IC2.29 JP4.8 Q2.1 GLCD.16 66.67,17.46 v68.58,15.56 | LED10.K 74.35,10.42 arc45 73.45,10.8
PD0
  Bottom 0.61: JP5.1 61.59,56.46 arc45 61.33,57.1 arc-45 60.96,57.99 60.96,75.51 arc-45 61.22,76.15
  Bottom 1.016: IC2.14 JP5.1 | 61.22,76.15 arc45 61.59,77.04 S22.10 S22.11
PD1
  Bottom 0.61: 66.67,77.98 S22.12 | JP5.2 59.05,56.31 arc-45 59.43,57.2 arc45 59.69,57.84 59.69,75.36 arc45 59.32,76.25
  Bottom 1.016: IC2.15 JP5.2 | 66.67,77.98 arc90 64.96,79.69 60.64,79.69 arc90 59.05,78.1 S22.9 59.05,76.89 arc45 59.32,76.25
PD2  (via drill 0.5 pad 1.27)
  Top 0.254: v46.67,40 v40.64,44.77
  Bottom 0.61: 46.35,40.32 56.14,50.11 | 56.51,51.01 IC2.16 | 46.35,40.32 v46.67,40 | 46.35,40.32 44.82,38.79 arc45 44.45,37.89 44.45,23.7 arc45 44.82,22.81 45.98,21.64 arc-45 46.36,20.75 | v40.64,44.77 36.88,48.52 arc45 35.99,48.9 28.47,48.9 arc-45 27.57,49.27 25.14,51.7
  Bottom 0.813: 56.14,50.11 arc45 56.51,51.01 | 25.14,51.7 arc-45 24.76,52.6 S21.8
  Bottom 1.016: IC2.16 JP5.3 56.51,56.31 arc-45 56.89,57.2 57.13,57.45 arc45 57.51,58.35 S18.2 S18.1 57.51,74.37 arc45 57.13,75.26 56.89,75.51 arc-45 56.51,76.41 S22.8 | GLCD.8 46.36,20.75
PD3
  Bottom 0.61: GLCD.7 | 43.82,21.06 arc45 43.44,21.96 arc-45 43.18,22.6 43.18,38.53 arc-45 43.55,39.42 53.6,49.48 | 53.97,55.25 49.07,60.15 arc45 48.17,60.52 46.89,60.52 arc-45 45.99,60.89 44.47,62.42 arc-45 44.09,63.31 S19.1
  Bottom 0.813: 53.6,49.48 arc45 53.97,50.37 IC2.17 | S19.1 S19.2
  Bottom 1.016: IC2.17 JP5.4 | LCD.6 41.27,13.13 arc-45 41.65,14.02 43.44,15.82 arc45 43.81,16.72 GLCD.7 | GLCD.7 43.82,21.06 | JP5.4 53.97,55.25 | S22.7 53.97,76.41 arc45 54.35,75.51 54.87,74.98 arc-45 55.24,74.09 55.24,59.13 arc-45 54.89,58.27 54.28,57.67 arc45 53.97,56.92 JP5.4
PD4
  Bottom 0.61: 39.41,15.56 39.48,15.56 | GLCD.6 | 34.52,68.26 arc-45 37.36,67.09 39.95,64.49 40.9,63.55 44.78,59.68 arc45 45.68,59.31 47.36,59.31 arc-45 48.26,58.93 51.06,56.13 arc-45 51.43,55.23 JP5.5 | 41.91,21.16 41.91,39.16 arc-45 42.28,40.06 51.06,48.84 arc45 51.43,49.74
  Bottom 0.813: 51.43,49.74 IC2.18
  Bottom 1.016: IC2.18 JP5.5 | LCD.4 36.19,12.34 arc-45 36.57,13.24 38.52,15.19 arc-45 39.41,15.56 | 39.48,15.56 arc45 40.38,15.93 41.27,16.83 GLCD.6 | 34.52,68.26 JDAC4.1 | GLCD.6 41.28,19.63 arc-45 41.54,20.27 arc45 41.91,21.16
PD5  (via drill 0.5 pad 1.27)
  Top 0.254: v19.05,73.03 v19.05,81.6
  Bottom 0.61: 31.12,31.54 arc-45 31.49,32.44 37.09,38.05 arc-45 37.99,38.42 38.21,38.42 arc45 39.11,38.79 48.52,48.21 arc45 48.89,49.1 | JP5.6 48.89,55.1 arc45 48.52,55.99 46.79,57.73 arc45 45.89,58.1 44.98,58.1 arc-45 44.08,58.47 36.96,65.59 arc45 35.11,66.36
  Bottom 0.813: 48.89,49.1 IC2.19
  Bottom 1.016: IC2.19 JP5.6 | GLCD.2 31.12,31.54 | JSPK.1 27.3,97.19 arc-45 26.83,96.05 26.43,95.64 arc45 26.03,94.69 26.03,89.43 arc-45 25.66,88.53 19.42,82.29 arc45 19.05,81.71 v19.05,81.6 | v19.05,73.03 19.05,70.34 arc42 19.38,69.49 21.85,66.77 arc48 22.79,66.36 35.11,66.36
PD6  (via drill 0.5 pad 1.27)
  Top 0.254: v38.1,62.55 v41.27,65.72
  Bottom 0.61: 43.02,44.61 38.47,40.06 arc-45 37.57,39.69 37.36,39.69 arc45 36.46,39.32 28.95,31.8 arc45 28.57,30.91 | 43.02,44.61 45.98,47.57 arc45 46.35,48.47 | GLCD.1 | JP5.7 arc45 46.01,55.76 45.31,56.46 arc45 44.41,56.83 44.34,56.83 arc-45 43.44,57.2 v38.1,62.55 | 43.02,44.61 42.54,45.08 | 42.54,45.08 38,49.63 arc45 37.1,50.01 29.89,50.01 arc-45 29,50.38 27.68,51.7 | 42.54,45.08 42.54,44.13 | 42.54,45.08 43.5,45.08
  Bottom 0.813: 46.35,48.47 IC2.20 | 27.68,51.7 arc-45 27.3,52.6 S21.7
  Bottom 1.016: IC2.20 JP5.7 | GLCD.1 28.57,30.91 | JRLY.1 45.72,77.28 arc-45 44.73,74.89 42.65,72.81 arc45 41.27,69.5 v41.27,65.72
PD7  (via drill 0.5 pad 1.27)
  Top 0.254: v46.35,38.1 v39.37,43.5 | v46.99,23.81 v69.21,23.81 | v37.46,45.72 v43.18,51.44
  Bottom 0.61: GLCD.17 | v39.37,43.5 37.46,45.4 v37.46,45.72 | v43.18,51.44 43.44,51.7
  Bottom 1.016: v46.35,38.1 IC2.21 46.35,24.97 arc45 46.73,24.08 v46.99,23.81 | v69.21,23.81 GLCD.17 | 43.44,51.7 arc45 43.81,52.6 JP5.8
RC
  Bottom 1.016: JDAC1.1 R11.A 109.11,42.12 arc45 111.12,46.98 R11.S
RS485_C
  Bottom 1.016: IC8.2 IC8.3 LED14.A JP9.1
RS485_RX  (via drill 0.5 pad 1.27)
  Top 0.254: v73.98,93.98 v71.44,96.52
  Bottom 1.016: S22.1 66.67,86.15 arc-45 67.05,87.05 v73.98,93.98 | v71.44,96.52 71.5,96.64 arc27 71.75,97.73 71.75,104.88 arc-45 72.13,105.78 73.29,106.94 arc-45 74.19,107.32 79.8,107.32 arc-45 80.7,106.94 81.47,106.18 arc-45 IC8.4
RS485_TX
  Bottom 1.016: S22.2 64.13,86.47 arc-45 64.51,87.37 73.92,96.78 arc45 74.29,97.68 IC8.1
RST
  Bottom 1.016: IC2.9 74.29,55.67 arc-45 74.67,56.57 75.19,57.1 arc45 75.56,57.99 75.56,72.07 arc90 C4.2 74.29,74.25 arc-45 74.7,75.22 S1.2 S1.1 BOOT.1 75.56,88.9 | 75.56,88.9 75.56,89.85 | 75.56,89.85 76.13,90.41 arc-45 77.84,91.12 ISP.6 | 74.93,89.47 R1.1 | 75.56,89.85 74.93,89.47 | 75.56,88.9 74.93,89.47
RTC_INT
  Bottom 0.61: S21.1 22.12,45.4 arc45 21.22,45.03 R29.1
  Bottom 1.016: IC6.7 arc-43 21.82,37.13 24.43,39.96 arc43 24.76,40.82 S21.1
RTS
  Bottom 0.406: IC1.3 60.71,94.44 arc45 61.08,93.54 61.22,93.4 arc-45 61.59,92.5 | 60.32,84.14 60.32,86.15 arc-45 60.7,87.05 61.22,87.58 arc45 61.59,88.47
  Bottom 0.813: 61.59,92.5 JP0.2 61.59,88.47
  Bottom 1.016: S22.5 56.51,84.51 arc45 56.78,83.87 arc45 57.68,83.5 59.16,83.5 arc45 60.06,83.87 60.32,84.14 60.59,83.87 arc45 61.49,83.5 67.42,83.5 arc45 68.32,83.87 69.48,85.04 arc-45 70.38,85.41 BOOT.2
SCL
  Bottom 0.61: 29.84,45.29 S21.3 | IC7.6 19.05,47.94 19.68,48.26 26.28,48.26 arc-45 27.49,47.76 27.68,47.57
  Bottom 0.813: S21.3 27.68,47.57
  Bottom 1.016: IC6.6 23.49,35.35 arc-45 23.87,36.25 R30.1 27.3,41.7 arc-45 27.68,42.6 29.47,44.4 arc45 29.84,45.29
SDA  (via drill 0.5 pad 1.27)
  Top 0.254: v29.84,42.23 v22.22,42.23
  Bottom 0.61: 32.38,45.29 S21.4
  Bottom 1.016: IC6.5 26.03,34.97 arc-50 26.49,35.94 R31.1 29.47,38.68 arc45 29.84,39.58 v29.84,42.23 32.01,44.4 arc45 32.38,45.29 | v22.22,42.23 20.21,42.23 arc-45 19.31,42.6 IC7.5
USB_RX
  Bottom 0.254: 60.32,90.17 60.32,92.71
  Bottom 0.406: 60.32,92.71 arc45 60.1,93.25 59.78,93.57 arc-45 59.41,94.47 IC1.5 | 59.43,87.68 59.95,88.21 arc45 60.32,89.11 60.32,90.17
  Bottom 0.813: S22.4 59.05,86.79 arc-45 59.43,87.68
USB_TX
  Bottom 0.406: 61.59,85.9 arc-45 61.97,86.8 65.67,90.5 arc45 66.04,91.4 66.04,91.87 arc45 65.67,92.76 65.14,93.29 arc45 64.24,93.66 64.03,93.66 arc-45 63.13,94.03 62.38,94.78 arc-45 62.01,95.68 IC1.1
  Bottom 0.813: S22.3 61.59,85.9
VUSB
  Bottom 1.016: FB1.2 49.44,110.32 arc45 50.34,110.7 X1.1
XT2
  Bottom 1.016: IC2.13 64.13,57.07 arc45 63.76,57.97 Q1.2 62.86,58.86 C7.1

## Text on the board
Bottom: iPhoenix | AVR | R.01 | 2012 | Designed By: | Walid Balid | eng.walid@al-awail.com
Document: SPK | 5VDC | OFF/ON | USB | RS485 | PS2 | B | A | 5VDC | R.01 | iPhoenix-AVR | 2012
tSilkScreen: SPEAKER | PS2 | OFF<> ON | USB | TX | RX | B | A | BUZ | +5Vdc | EXT | USB | RS485 | ON | PS2 | USB | SOUND | IR | D | RELAY | BOOT | RST | SCK | MISO | MOSI | GND | +5V | 7-Segment | USB | RS | 1 | 2 | 3 | A | +5V | +5V | RLY | GND | 4 | 5 | 6 | B | GND | RESET | GND | SW2 | SW1 | OUT | 7 | 8 | 9 | C | PWM-DAC | GND | +5V | * | 0 | # | D | PD7 | PD6 | PD5 | PD4 | PD3 | PD2 | PD1 | PB7 | PB6 | PB5 | PB4 | PB3 | PB2 | PB1 | PB0 | PPS | WRP | SCL | SDA | PD0 | VAR | AIN1 | RC | AVR-MCU | EPROM | ATmega32A | POT0 | SW3 | VAR1 | CAP | AIN0 | GLCD | RTC | PC0 | PC1 | PC2 | PC3 | PC4 | PC5 | PC6 | PC7 | LM35 | POT1 | PA7 | PA6 | PA5 | PA4 | PA3 | PA2 | PA1 | PA0 | DS1820 | LDR | VAR0 | NTC | GLCD | LCD | D1 | D8 | LEDs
